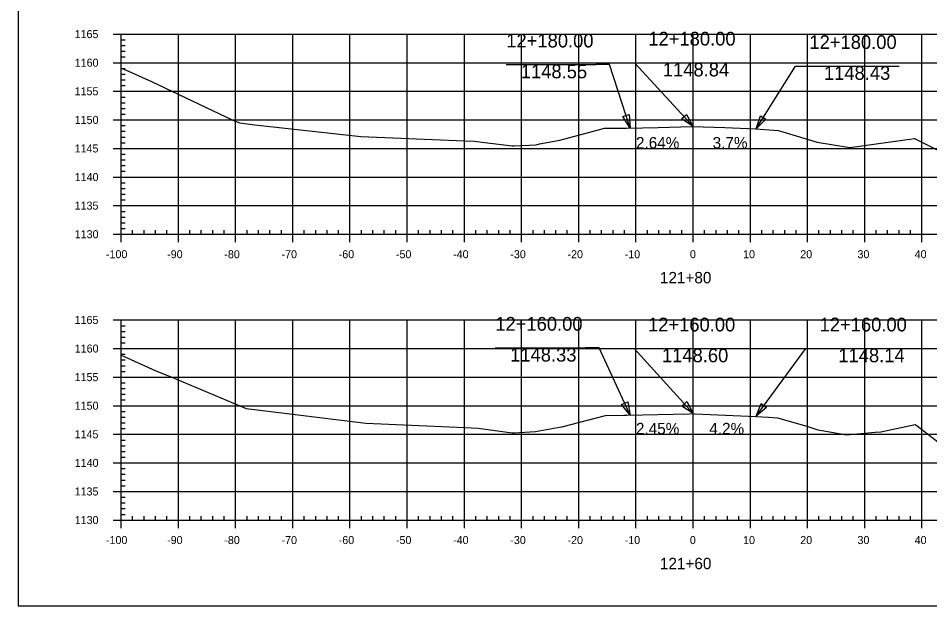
# Model space of a CAD drawing. Extents: x 688474 to 694748, y 765018 to 767373.
# Drawn here: x 690038.3 to 690197.7, y 765298.3 to 765401.1 of the extents above; entities that cross this region are included whole.
import ezdxf

# ---------------------------------------------------------------- set-up
doc = ezdxf.new("R2010")
doc.units = 0
for name, color, linetype in [('60', 7, 'Continuous'), ('Default', 7, 'Continuous'), ('R_Exist Surface', 7, 'Continuous'), ('R_Grid', 7, 'Continuous'), ('R_No Plot', 7, 'Continuous'), ('R_Xsect Slope', 7, 'Continuous')]:
    doc.layers.add(name, color=color, linetype=linetype)

msp = doc.modelspace()

# ---------------------------------------------------------------- linework, layer by layer
at = {"layer": '60'}
for p, q in [((690054.91, 765398.32), (690057.71, 765398.32)), ((690056.31, 765363.32), (690056.31, 765398.32)), ((690056.31, 765397.32), (690057.01, 765397.32)), ((690056.31, 765396.32), (690057.01, 765396.32)), ((690056.31, 765395.32), (690057.01, 765395.32)), ((690054.91, 765393.32), (690057.71, 765393.32)), ((690056.31, 765394.32), (690057.01, 765394.32)), ((690056.31, 765392.32), (690057.01, 765392.32)), ((690056.31, 765391.32), (690057.01, 765391.32)), ((690056.31, 765390.32), (690057.01, 765390.32)), ((690056.31, 765389.32), (690057.01, 765389.32)), ((690054.91, 765388.32), (690057.71, 765388.32)), ((690056.31, 765387.32), (690057.01, 765387.32)), ((690056.31, 765386.32), (690057.01, 765386.32)), ((690056.31, 765385.32), (690057.01, 765385.32)), ((690056.31, 765384.32), (690057.01, 765384.32)), ((690054.91, 765383.32), (690057.71, 765383.32)), ((690056.31, 765382.32), (690057.01, 765382.32)), ((690056.31, 765381.32), (690057.01, 765381.32)), ((690056.31, 765380.32), (690057.01, 765380.32)), ((690056.31, 765379.32), (690057.01, 765379.32)), ((690054.91, 765378.32), (690057.71, 765378.32)), ((690056.31, 765377.32), (690057.01, 765377.32)), ((690056.31, 765376.32), (690057.01, 765376.32)), ((690056.31, 765375.32), (690057.01, 765375.32)), ((690056.31, 765374.32), (690057.01, 765374.32)), ((690054.91, 765373.32), (690057.71, 765373.32)), ((690056.31, 765372.32), (690057.01, 765372.32)), ((690056.31, 765371.32), (690057.01, 765371.32)), ((690056.31, 765370.32), (690057.01, 765370.32)), ((690054.91, 765368.32), (690057.71, 765368.32)), ((690056.31, 765369.32), (690057.01, 765369.32)), ((690056.31, 765367.32), (690057.01, 765367.32)), ((690056.31, 765366.32), (690057.01, 765366.32)), ((690056.31, 765365.32), (690057.01, 765365.32)), ((690056.31, 765361.92), (690056.31, 765364.72)), ((690066.31, 765361.92), (690066.31, 765364.72)), ((690076.31, 765361.92), (690076.31, 765364.72)), ((690086.31, 765361.92), (690086.31, 765364.72)), ((690096.31, 765361.92), (690096.31, 765364.72)), ((690106.31, 765361.92), (690106.31, 765364.72)), ((690116.31, 765361.92), (690116.31, 765364.72)), ((690126.31, 765361.92), (690126.31, 765364.72)), ((690136.31, 765361.92), (690136.31, 765364.72)), ((690146.31, 765361.92), (690146.31, 765364.72)), ((690156.31, 765361.92), (690156.31, 765364.72)), ((690166.31, 765361.92), (690166.31, 765364.72)), ((690176.31, 765361.92), (690176.31, 765364.72)), ((690186.31, 765361.92), (690186.31, 765364.72)), ((690196.31, 765361.92), (690196.31, 765364.72)), ((690054.91, 765363.32), (690057.71, 765363.32)), ((690056.31, 765364.32), (690057.01, 765364.32)), ((690056.31, 765363.32), (690256.31, 765363.32)), ((690058.31, 765363.32), (690058.31, 765364.02)), ((690060.31, 765363.32), (690060.31, 765364.02)), ((690062.31, 765363.32), (690062.31, 765364.02)), ((690064.31, 765363.32), (690064.31, 765364.02)), ((690068.31, 765363.32), (690068.31, 765364.02)), ((690070.31, 765363.32), (690070.31, 765364.02)), ((690072.31, 765363.32), (690072.31, 765364.02)), ((690074.31, 765363.32), (690074.31, 765364.02)), ((690078.31, 765363.32), (690078.31, 765364.02)), ((690080.31, 765363.32), (690080.31, 765364.02)), ((690082.31, 765363.32), (690082.31, 765364.02)), ((690084.31, 765363.32), (690084.31, 765364.02)), ((690088.31, 765363.32), (690088.31, 765364.02)), ((690090.31, 765363.32), (690090.31, 765364.02)), ((690092.31, 765363.32), (690092.31, 765364.02)), ((690094.31, 765363.32), (690094.31, 765364.02)), ((690098.31, 765363.32), (690098.31, 765364.02)), ((690100.31, 765363.32), (690100.31, 765364.02)), ((690102.31, 765363.32), (690102.31, 765364.02)), ((690104.31, 765363.32), (690104.31, 765364.02)), ((690108.31, 765363.32), (690108.31, 765364.02)), ((690110.31, 765363.32), (690110.31, 765364.02)), ((690112.31, 765363.32), (690112.31, 765364.02)), ((690114.31, 765363.32), (690114.31, 765364.02)), ((690118.31, 765363.32), (690118.31, 765364.02)), ((690120.31, 765363.32), (690120.31, 765364.02)), ((690122.31, 765363.32), (690122.31, 765364.02)), ((690124.31, 765363.32), (690124.31, 765364.02)), ((690128.31, 765363.32), (690128.31, 765364.02)), ((690130.31, 765363.32), (690130.31, 765364.02)), ((690132.31, 765363.32), (690132.31, 765364.02)), ((690134.31, 765363.32), (690134.31, 765364.02)), ((690138.31, 765363.32), (690138.31, 765364.02)), ((690140.31, 765363.32), (690140.31, 765364.02)), ((690142.31, 765363.32), (690142.31, 765364.02)), ((690144.31, 765363.32), (690144.31, 765364.02)), ((690148.31, 765363.32), (690148.31, 765364.02)), ((690150.31, 765363.32), (690150.31, 765364.02)), ((690152.31, 765363.32), (690152.31, 765364.02)), ((690154.31, 765363.32), (690154.31, 765364.02)), ((690158.31, 765363.32), (690158.31, 765364.02)), ((690160.31, 765363.32), (690160.31, 765364.02)), ((690162.31, 765363.32), (690162.31, 765364.02)), ((690164.31, 765363.32), (690164.31, 765364.02)), ((690168.31, 765363.32), (690168.31, 765364.02)), ((690170.31, 765363.32), (690170.31, 765364.02)), ((690172.31, 765363.32), (690172.31, 765364.02)), ((690174.31, 765363.32), (690174.31, 765364.02)), ((690178.31, 765363.32), (690178.31, 765364.02)), ((690180.31, 765363.32), (690180.31, 765364.02)), ((690182.31, 765363.32), (690182.31, 765364.02)), ((690184.31, 765363.32), (690184.31, 765364.02)), ((690188.31, 765363.32), (690188.31, 765364.02)), ((690190.31, 765363.32), (690190.31, 765364.02)), ((690192.31, 765363.32), (690192.31, 765364.02)), ((690194.31, 765363.32), (690194.31, 765364.02)), ((690054.91, 765348.32), (690057.71, 765348.32)), ((690056.31, 765313.32), (690056.31, 765348.32)), ((690056.31, 765347.32), (690057.01, 765347.32)), ((690056.31, 765346.32), (690057.01, 765346.32)), ((690056.31, 765345.32), (690057.01, 765345.32)), ((690056.31, 765344.32), (690057.01, 765344.32)), ((690054.91, 765343.32), (690057.71, 765343.32)), ((690056.31, 765342.32), (690057.01, 765342.32)), ((690056.31, 765341.32), (690057.01, 765341.32)), ((690056.31, 765340.32), (690057.01, 765340.32)), ((690056.31, 765339.32), (690057.01, 765339.32)), ((690054.91, 765338.32), (690057.71, 765338.32)), ((690056.31, 765337.32), (690057.01, 765337.32)), ((690056.31, 765336.32), (690057.01, 765336.32)), ((690056.31, 765335.32), (690057.01, 765335.32)), ((690056.31, 765334.32), (690057.01, 765334.32)), ((690054.91, 765333.32), (690057.71, 765333.32)), ((690056.31, 765332.32), (690057.01, 765332.32)), ((690056.31, 765331.32), (690057.01, 765331.32)), ((690056.31, 765330.32), (690057.01, 765330.32)), ((690054.91, 765328.32), (690057.71, 765328.32)), ((690056.31, 765329.32), (690057.01, 765329.32)), ((690056.31, 765327.32), (690057.01, 765327.32)), ((690056.31, 765326.32), (690057.01, 765326.32)), ((690056.31, 765325.32), (690057.01, 765325.32)), ((690054.91, 765323.32), (690057.71, 765323.32)), ((690056.31, 765324.32), (690057.01, 765324.32)), ((690056.31, 765322.32), (690057.01, 765322.32)), ((690056.31, 765321.32), (690057.01, 765321.32)), ((690056.31, 765320.32), (690057.01, 765320.32)), ((690056.31, 765319.32), (690057.01, 765319.32)), ((690054.91, 765318.32), (690057.71, 765318.32)), ((690056.31, 765317.32), (690057.01, 765317.32)), ((690056.31, 765316.32), (690057.01, 765316.32)), ((690056.31, 765315.32), (690057.01, 765315.32)), ((690056.31, 765311.92), (690056.31, 765314.72)), ((690056.31, 765314.32), (690057.01, 765314.32)), ((690058.31, 765313.32), (690058.31, 765314.02)), ((690060.31, 765313.32), (690060.31, 765314.02)), ((690062.31, 765313.32), (690062.31, 765314.02)), ((690064.31, 765313.32), (690064.31, 765314.02)), ((690066.31, 765311.92), (690066.31, 765314.72)), ((690068.31, 765313.32), (690068.31, 765314.02)), ((690070.31, 765313.32), (690070.31, 765314.02)), ((690072.31, 765313.32), (690072.31, 765314.02)), ((690074.31, 765313.32), (690074.31, 765314.02)), ((690076.31, 765311.92), (690076.31, 765314.72)), ((690078.31, 765313.32), (690078.31, 765314.02)), ((690080.31, 765313.32), (690080.31, 765314.02)), ((690082.31, 765313.32), (690082.31, 765314.02)), ((690084.31, 765313.32), (690084.31, 765314.02)), ((690086.31, 765311.92), (690086.31, 765314.72)), ((690088.31, 765313.32), (690088.31, 765314.02)), ((690090.31, 765313.32), (690090.31, 765314.02)), ((690092.31, 765313.32), (690092.31, 765314.02)), ((690094.31, 765313.32), (690094.31, 765314.02)), ((690096.31, 765311.92), (690096.31, 765314.72)), ((690098.31, 765313.32), (690098.31, 765314.02)), ((690100.31, 765313.32), (690100.31, 765314.02)), ((690102.31, 765313.32), (690102.31, 765314.02)), ((690104.31, 765313.32), (690104.31, 765314.02)), ((690106.31, 765311.92), (690106.31, 765314.72)), ((690108.31, 765313.32), (690108.31, 765314.02)), ((690110.31, 765313.32), (690110.31, 765314.02)), ((690112.31, 765313.32), (690112.31, 765314.02)), ((690114.31, 765313.32), (690114.31, 765314.02)), ((690116.31, 765311.92), (690116.31, 765314.72)), ((690118.31, 765313.32), (690118.31, 765314.02)), ((690120.31, 765313.32), (690120.31, 765314.02)), ((690122.31, 765313.32), (690122.31, 765314.02)), ((690124.31, 765313.32), (690124.31, 765314.02)), ((690126.31, 765311.92), (690126.31, 765314.72)), ((690128.31, 765313.32), (690128.31, 765314.02)), ((690130.31, 765313.32), (690130.31, 765314.02)), ((690132.31, 765313.32), (690132.31, 765314.02)), ((690134.31, 765313.32), (690134.31, 765314.02)), ((690136.31, 765311.92), (690136.31, 765314.72)), ((690138.31, 765313.32), (690138.31, 765314.02)), ((690140.31, 765313.32), (690140.31, 765314.02)), ((690142.31, 765313.32), (690142.31, 765314.02)), ((690144.31, 765313.32), (690144.31, 765314.02)), ((690146.31, 765311.92), (690146.31, 765314.72)), ((690148.31, 765313.32), (690148.31, 765314.02)), ((690150.31, 765313.32), (690150.31, 765314.02)), ((690152.31, 765313.32), (690152.31, 765314.02)), ((690154.31, 765313.32), (690154.31, 765314.02)), ((690156.31, 765311.92), (690156.31, 765314.72)), ((690158.31, 765313.32), (690158.31, 765314.02)), ((690160.31, 765313.32), (690160.31, 765314.02)), ((690162.31, 765313.32), (690162.31, 765314.02)), ((690164.31, 765313.32), (690164.31, 765314.02)), ((690166.31, 765311.92), (690166.31, 765314.72)), ((690168.31, 765313.32), (690168.31, 765314.02)), ((690170.31, 765313.32), (690170.31, 765314.02)), ((690172.31, 765313.32), (690172.31, 765314.02)), ((690174.31, 765313.32), (690174.31, 765314.02)), ((690176.31, 765311.92), (690176.31, 765314.72)), ((690178.31, 765313.32), (690178.31, 765314.02)), ((690180.31, 765313.32), (690180.31, 765314.02)), ((690182.31, 765313.32), (690182.31, 765314.02)), ((690184.31, 765313.32), (690184.31, 765314.02)), ((690186.31, 765311.92), (690186.31, 765314.72)), ((690188.31, 765313.32), (690188.31, 765314.02)), ((690190.31, 765313.32), (690190.31, 765314.02)), ((690192.31, 765313.32), (690192.31, 765314.02)), ((690194.31, 765313.32), (690194.31, 765314.02)), ((690196.31, 765311.92), (690196.31, 765314.72)), ((690054.91, 765313.32), (690057.71, 765313.32)), ((690056.31, 765313.32), (690256.31, 765313.32))]:
    msp.add_line(p, q, dxfattribs=at)
at = {"layer": 'R_Exist Surface'}
for p, q in [((690148.47, 765393.32), (690164.14, 765393.32)), ((690123.63, 765392.99), (690139.3, 765392.99)), ((690176.63, 765392.72), (690192.3, 765392.72)), ((690121.71, 765343.44), (690137.5, 765343.44)), ((690148.41, 765343.32), (690164.2, 765343.32)), ((690178.41, 765343.32), (690194.2, 765343.32))]:
    msp.add_line(p, q, dxfattribs=at)
for points in [[(690156.31, 765382.17), (690146.07, 765393.32), (690148.47, 765393.32)], [(690056.31, 765392.36), (690057.08, 765392.05), (690061.59, 765390.06), (690075.8, 765383.29), (690077, 765382.78), (690079.7, 765382.45), (690098.21, 765380.4), (690116.32, 765379.65), (690118.08, 765379.59), (690119.91, 765379.35), (690124.65, 765378.77), (690125.04, 765378.79), (690126.42, 765378.85), (690128.84, 765378.97), (690129.43, 765379.1), (690132.99, 765379.79), (690137.99, 765381.1), (690140.8, 765381.85), (690141.97, 765381.85), (690144.71, 765381.86), (690150.19, 765382.01), (690156.12, 765382.17), (690161.86, 765381.97), (690167.28, 765381.76), (690170.37, 765381.54), (690171.19, 765381.48), (690171.99, 765381.24), (690178.02, 765379.43), (690180.86, 765378.96), (690183.72, 765378.5), (690195.03, 765380.04), (690195.05, 765380.04), (690195.14, 765380), (690212.16, 765371.57)], [(690145.31, 765381.88), (690141.7, 765392.99), (690139.3, 765392.99)], [(690167.31, 765381.76), (690174.23, 765392.72), (690176.63, 765392.72)], [(690145.31, 765331.65), (690139.9, 765343.44), (690137.5, 765343.44)], [(690156.31, 765331.93), (690146.01, 765343.32), (690148.41, 765343.32)], [(690167.31, 765331.47), (690176.01, 765343.32), (690178.41, 765343.32)], [(690056.31, 765342.16), (690057.35, 765341.67), (690062.39, 765339.41), (690064.85, 765338.44), (690078.17, 765332.82), (690085.3, 765331.94), (690099.08, 765330.26), (690115.07, 765329.55), (690118.7, 765329.42), (690124.64, 765328.6), (690124.76, 765328.59), (690125.01, 765328.6), (690128.77, 765328.82), (690133.21, 765329.6), (690133.41, 765329.64), (690133.58, 765329.68), (690140.96, 765331.63), (690144.18, 765331.64), (690144.7, 765331.64), (690155.63, 765331.91), (690156.13, 765331.93), (690156.63, 765331.91), (690167.34, 765331.46), (690169.5, 765331.32), (690171.08, 765331.21), (690176.18, 765329.72), (690178.13, 765329.12), (690179.49, 765328.88), (690183.11, 765328.24), (690188.12, 765328.68), (690189.13, 765328.76), (690194.31, 765329.86), (690195.12, 765330.03), (690195.45, 765329.82), (690206.05, 765321.64)]]:
    msp.add_lwpolyline(points, dxfattribs=at)
for points in [[(690145.31, 765381.88), (690144.03, 765383.91), (690145.14, 765384.27)], [(690156.31, 765382.17), (690154.3, 765383.49), (690155.16, 765384.28)], [(690167.31, 765381.76), (690168.06, 765384.04), (690169.04, 765383.42)], [(690145.31, 765331.65), (690143.8, 765333.53), (690144.86, 765334.01)], [(690156.31, 765331.93), (690154.31, 765333.27), (690155.18, 765334.05)], [(690167.31, 765331.47), (690168.21, 765333.69), (690169.15, 765333)]]:
    msp.add_lwpolyline(points, close=True, dxfattribs=at)
at = {"layer": 'R_Grid'}
for p, q in [((690056.31, 765398.32), (690256.31, 765398.32)), ((690056.31, 765363.32), (690056.31, 765398.32)), ((690066.31, 765363.32), (690066.31, 765398.32)), ((690076.31, 765363.32), (690076.31, 765398.32)), ((690086.31, 765363.32), (690086.31, 765398.32)), ((690096.31, 765363.32), (690096.31, 765398.32)), ((690106.31, 765363.32), (690106.31, 765398.32)), ((690116.31, 765363.32), (690116.31, 765398.32)), ((690126.31, 765363.32), (690126.31, 765398.32)), ((690136.31, 765363.32), (690136.31, 765398.32)), ((690146.31, 765363.32), (690146.31, 765398.32)), ((690156.31, 765363.32), (690156.31, 765398.32)), ((690166.31, 765363.32), (690166.31, 765398.32)), ((690176.31, 765363.32), (690176.31, 765398.32)), ((690186.31, 765363.32), (690186.31, 765398.32)), ((690196.31, 765363.32), (690196.31, 765398.32)), ((690056.31, 765393.32), (690256.31, 765393.32)), ((690056.31, 765388.32), (690256.31, 765388.32)), ((690056.31, 765383.32), (690256.31, 765383.32)), ((690056.31, 765378.32), (690256.31, 765378.32)), ((690056.31, 765373.32), (690256.31, 765373.32)), ((690056.31, 765368.32), (690256.31, 765368.32)), ((690056.31, 765363.32), (690256.31, 765363.32)), ((690056.31, 765348.32), (690256.31, 765348.32)), ((690056.31, 765313.32), (690056.31, 765348.32)), ((690066.31, 765313.32), (690066.31, 765348.32)), ((690076.31, 765313.32), (690076.31, 765348.32)), ((690086.31, 765313.32), (690086.31, 765348.32)), ((690096.31, 765313.32), (690096.31, 765348.32)), ((690106.31, 765313.32), (690106.31, 765348.32)), ((690116.31, 765313.32), (690116.31, 765348.32)), ((690126.31, 765313.32), (690126.31, 765348.32)), ((690136.31, 765313.32), (690136.31, 765348.32)), ((690146.31, 765313.32), (690146.31, 765348.32)), ((690156.31, 765313.32), (690156.31, 765348.32)), ((690166.31, 765313.32), (690166.31, 765348.32)), ((690176.31, 765313.32), (690176.31, 765348.32)), ((690186.31, 765313.32), (690186.31, 765348.32)), ((690196.31, 765313.32), (690196.31, 765348.32)), ((690056.31, 765343.32), (690256.31, 765343.32)), ((690056.31, 765338.32), (690256.31, 765338.32)), ((690056.31, 765333.32), (690256.31, 765333.32)), ((690056.31, 765328.32), (690256.31, 765328.32)), ((690056.31, 765323.32), (690256.31, 765323.32)), ((690056.31, 765318.32), (690256.31, 765318.32)), ((690056.31, 765313.32), (690256.31, 765313.32))]:
    msp.add_line(p, q, dxfattribs=at)
at = {"layer": 'R_No Plot'}
msp.add_lwpolyline([(690038.31, 765298.32), (690354.49, 765298.32), (690354.49, 765503.78), (690038.31, 765503.78)], close=True, dxfattribs=at)

# ---------------------------------------------------------------- texts
at = {"layer": '60'}
for s, height, p in [('1165', 1.4, (690048.16, 765397.62)), ('1160', 1.4, (690048.18, 765392.62)), ('1155', 1.4, (690048.16, 765387.62)), ('1150', 1.4, (690048.18, 765382.62)), ('1145', 1.4, (690048.16, 765377.62)), ('1140', 1.4, (690048.18, 765372.62)), ('1135', 1.4, (690048.16, 765367.62)), ('1130', 1.4, (690048.18, 765362.62)), ('-100', 1.4, (690053.64, 765359.12)), ('-90', 1.4, (690064.34, 765359.12)), ('-80', 1.4, (690074.34, 765359.12)), ('-70', 1.4, (690084.34, 765359.12)), ('-60', 1.4, (690094.34, 765359.12)), ('-50', 1.4, (690104.34, 765359.12)), ('-40', 1.4, (690114.34, 765359.12)), ('-30', 1.4, (690124.34, 765359.12)), ('-20', 1.4, (690134.34, 765359.12)), ('-10', 1.4, (690144.34, 765359.12)), ('0', 1.4, (690155.74, 765359.12)), ('10', 1.4, (690165.04, 765359.12)), ('20', 1.4, (690175.04, 765359.12)), ('30', 1.4, (690185.04, 765359.12)), ('40', 1.4, (690195.04, 765359.12)), ('121+80', 2, (690150.5, 765354.72)), ('1165', 1.4, (690048.16, 765347.62)), ('1160', 1.4, (690048.18, 765342.62)), ('1155', 1.4, (690048.16, 765337.62)), ('1150', 1.4, (690048.18, 765332.62)), ('1145', 1.4, (690048.16, 765327.62)), ('1140', 1.4, (690048.18, 765322.62)), ('1135', 1.4, (690048.16, 765317.62)), ('1130', 1.4, (690048.18, 765312.62)), ('-100', 1.4, (690053.64, 765309.12)), ('-90', 1.4, (690064.34, 765309.12)), ('-80', 1.4, (690074.34, 765309.12)), ('-70', 1.4, (690084.34, 765309.12)), ('-60', 1.4, (690094.34, 765309.12)), ('-50', 1.4, (690104.34, 765309.12)), ('-40', 1.4, (690114.34, 765309.12)), ('-30', 1.4, (690124.34, 765309.12)), ('-20', 1.4, (690134.34, 765309.12)), ('-10', 1.4, (690144.34, 765309.12)), ('0', 1.4, (690155.74, 765309.12)), ('10', 1.4, (690165.04, 765309.12)), ('20', 1.4, (690175.04, 765309.12)), ('30', 1.4, (690185.04, 765309.12)), ('40', 1.4, (690195.04, 765309.12)), ('121+60', 2, (690150.5, 765304.72))]:
    msp.add_text(s, height=height, dxfattribs=at).set_placement(p)
at = {"layer": 'Default'}
for s, p in [('2.64%', (690146.31, 765378.32)), ('3.7%', (690159.72, 765378.32)), ('2.45%', (690146.31, 765328.32)), ('4.2%', (690159.13, 765328.32))]:
    msp.add_text(s, height=2, dxfattribs=at).set_placement(p)
at = {"layer": 'R_Xsect Slope'}
for s, p in [('12+180.00', (690123.63, 765395.99)), ('12+180.00', (690148.47, 765396.32)), ('12+180.00', (690176.63, 765395.72)), ('1148.84', (690151.01, 765390.92)), ('1148.55', (690126.17, 765390.59)), ('1148.43', (690179.17, 765390.32)), ('12+160.00', (690121.71, 765346.44)), ('12+160.00', (690148.41, 765346.32)), ('12+160.00', (690178.41, 765346.32)), ('1148.33', (690124.31, 765341.04)), ('1148.60', (690150.85, 765340.92)), ('1148.14', (690181.69, 765340.92))]:
    msp.add_text(s, height=2.4, dxfattribs=at).set_placement(p)

doc.saveas('drawing.dxf')
